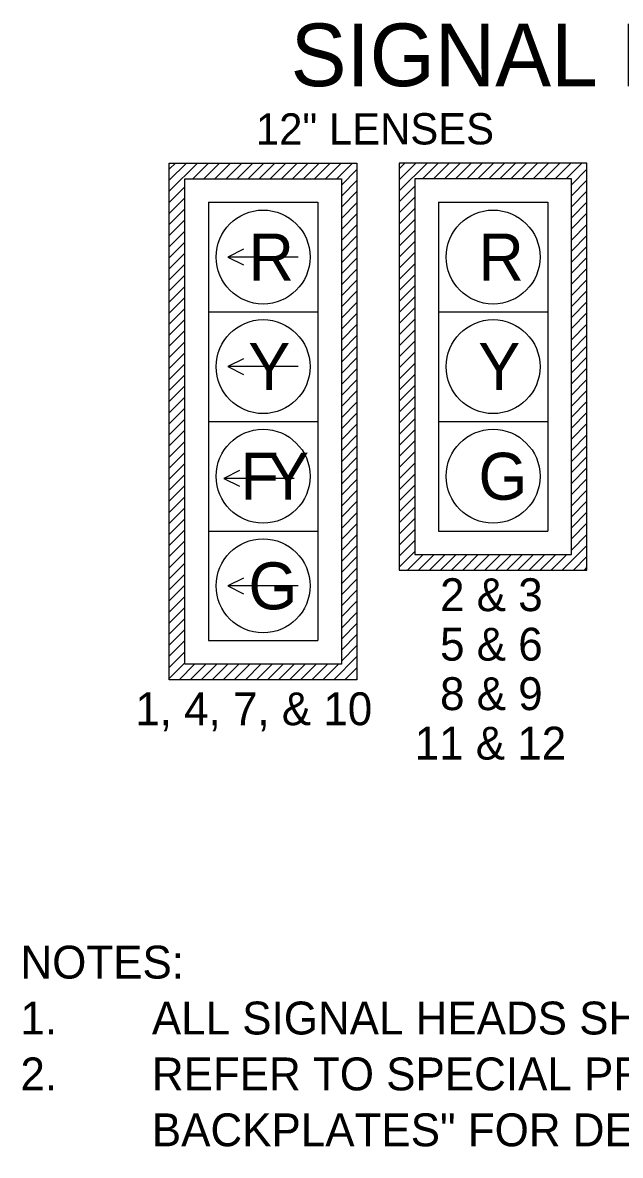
# Model space of a CAD drawing. Extents: x 418532 to 419834, y -565899 to -565285.
# Drawn here: x 419060.8 to 419137.2, y -565430.1 to -565285.5 of the extents above; entities that cross this region are included whole.
import ezdxf

# ---------------------------------------------------------------- set-up
doc = ezdxf.new("R2010")
doc.units = 0
for name, color, linetype in [('C-ANNO-TEXT', 7, 'Continuous'), ('Level 61', 7, 'Continuous'), ('T_Drafting', 7, 'Continuous')]:
    doc.layers.add(name, color=color, linetype=linetype)

msp = doc.modelspace()

# ---------------------------------------------------------------- linework, layer by layer
at = {"layer": 'T_Drafting'}
for p, q in [((419079.58, -565369.4), (419079.58, -565303.4)), ((419079.58, -565303.4), (419103.58, -565303.4)), ((419079.58, -565307), (419083.19, -565303.4)), ((419079.58, -565305.59), (419081.77, -565303.4)), ((419079.58, -565304.18), (419080.36, -565303.4)), ((419082.6, -565305.4), (419084.6, -565303.4)), ((419084.02, -565305.4), (419086.02, -565303.4)), ((419085.43, -565305.4), (419087.43, -565303.4)), ((419086.84, -565305.4), (419088.84, -565303.4)), ((419088.26, -565305.4), (419090.26, -565303.4)), ((419089.67, -565305.4), (419091.67, -565303.4)), ((419091.09, -565305.4), (419093.09, -565303.4)), ((419092.5, -565305.4), (419094.5, -565303.4)), ((419093.92, -565305.4), (419095.92, -565303.4)), ((419095.33, -565305.4), (419097.33, -565303.4)), ((419096.74, -565305.4), (419098.74, -565303.4)), ((419098.16, -565305.4), (419100.16, -565303.4)), ((419099.57, -565305.4), (419101.57, -565303.4)), ((419100.99, -565305.4), (419102.99, -565303.4)), ((419103.58, -565303.4), (419103.58, -565369.4)), ((419132.98, -565303.4), (419108.98, -565303.4)), ((419108.98, -565303.4), (419108.98, -565355.4)), ((419108.98, -565306.94), (419112.53, -565303.4)), ((419108.98, -565305.53), (419111.11, -565303.4)), ((419108.98, -565304.12), (419109.7, -565303.4)), ((419111.94, -565305.4), (419113.94, -565303.4)), ((419113.35, -565305.4), (419115.35, -565303.4)), ((419114.77, -565305.4), (419116.77, -565303.4)), ((419116.18, -565305.4), (419118.18, -565303.4)), ((419117.6, -565305.4), (419119.6, -565303.4)), ((419119.01, -565305.4), (419121.01, -565303.4)), ((419120.42, -565305.4), (419122.42, -565303.4)), ((419121.84, -565305.4), (419123.84, -565303.4)), ((419123.25, -565305.4), (419125.25, -565303.4)), ((419124.67, -565305.4), (419126.67, -565303.4)), ((419126.08, -565305.4), (419128.08, -565303.4)), ((419127.5, -565305.4), (419129.5, -565303.4)), ((419128.91, -565305.4), (419130.91, -565303.4)), ((419130.32, -565305.4), (419132.32, -565303.4)), ((419132.98, -565355.4), (419132.98, -565303.4)), ((419101.58, -565306.22), (419103.58, -565304.22)), ((419130.98, -565306.16), (419132.98, -565304.16)), ((419079.58, -565308.42), (419081.58, -565306.42)), ((419101.58, -565307.63), (419103.58, -565305.63)), ((419108.98, -565308.36), (419110.98, -565306.36)), ((419130.98, -565307.57), (419132.98, -565305.57)), ((419079.58, -565309.83), (419081.58, -565307.83)), ((419101.58, -565309.05), (419103.58, -565307.05)), ((419108.98, -565309.77), (419110.98, -565307.77)), ((419130.98, -565308.99), (419132.98, -565306.99)), ((419079.58, -565311.25), (419081.58, -565309.25)), ((419084.58, -565308.4), (419098.58, -565308.4)), ((419084.58, -565308.4), (419084.58, -565322.4)), ((419098.58, -565308.4), (419098.58, -565322.4)), ((419101.58, -565310.46), (419103.58, -565308.46)), ((419108.98, -565311.19), (419110.98, -565309.19)), ((419113.98, -565308.4), (419127.98, -565308.4)), ((419113.98, -565308.4), (419113.98, -565322.4)), ((419127.98, -565308.4), (419127.98, -565322.4)), ((419130.98, -565310.4), (419132.98, -565308.4)), ((419130.98, -565311.81), (419132.98, -565309.81)), ((419079.58, -565312.66), (419081.58, -565310.66)), ((419101.58, -565311.87), (419103.58, -565309.87)), ((419108.98, -565312.6), (419110.98, -565310.6)), ((419130.98, -565313.23), (419132.98, -565311.23)), ((419079.58, -565314.08), (419081.58, -565312.08)), ((419101.58, -565313.29), (419103.58, -565311.29)), ((419101.58, -565314.7), (419103.58, -565312.7)), ((419108.98, -565314.01), (419110.98, -565312.01)), ((419130.98, -565314.64), (419132.98, -565312.64)), ((419079.58, -565315.49), (419081.58, -565313.49)), ((419101.58, -565316.12), (419103.58, -565314.12)), ((419108.98, -565315.43), (419110.98, -565313.43)), ((419130.98, -565316.06), (419132.98, -565314.06)), ((419079.58, -565316.9), (419081.58, -565314.9)), ((419096.08, -565315.4), (419087.08, -565315.4)), ((419101.58, -565317.53), (419103.58, -565315.53)), ((419108.98, -565316.84), (419110.98, -565314.84)), ((419130.98, -565317.47), (419132.98, -565315.47)), ((419079.58, -565318.32), (419081.58, -565316.32)), ((419101.58, -565318.95), (419103.58, -565316.95)), ((419108.98, -565318.26), (419110.98, -565316.26)), ((419130.98, -565318.88), (419132.98, -565316.88)), ((419079.58, -565319.73), (419081.58, -565317.73)), ((419101.58, -565320.36), (419103.58, -565318.36)), ((419108.98, -565319.67), (419110.98, -565317.67)), ((419130.98, -565320.3), (419132.98, -565318.3)), ((419079.58, -565321.15), (419081.58, -565319.15)), ((419101.58, -565321.77), (419103.58, -565319.77)), ((419108.98, -565321.09), (419110.98, -565319.09)), ((419130.98, -565321.71), (419132.98, -565319.71)), ((419079.58, -565322.56), (419081.58, -565320.56)), ((419101.58, -565323.19), (419103.58, -565321.19)), ((419108.98, -565322.5), (419110.98, -565320.5)), ((419130.98, -565323.13), (419132.98, -565321.13)), ((419079.58, -565323.97), (419081.58, -565321.97)), ((419084.58, -565322.4), (419098.58, -565322.4)), ((419084.58, -565322.4), (419084.58, -565336.4)), ((419098.58, -565322.4), (419098.58, -565336.4)), ((419101.58, -565324.6), (419103.58, -565322.6)), ((419108.98, -565323.91), (419110.98, -565321.91)), ((419113.98, -565322.4), (419127.98, -565322.4)), ((419113.98, -565322.4), (419113.98, -565336.4)), ((419127.98, -565322.4), (419127.98, -565336.4)), ((419130.98, -565324.54), (419132.98, -565322.54)), ((419079.58, -565325.39), (419081.58, -565323.39)), ((419101.58, -565326.02), (419103.58, -565324.02)), ((419108.98, -565325.33), (419110.98, -565323.33)), ((419130.98, -565325.96), (419132.98, -565323.96)), ((419079.58, -565326.8), (419081.58, -565324.8)), ((419101.58, -565327.43), (419103.58, -565325.43)), ((419108.98, -565326.74), (419110.98, -565324.74)), ((419130.98, -565327.37), (419132.98, -565325.37)), ((419079.58, -565328.22), (419081.58, -565326.22)), ((419101.58, -565328.84), (419103.58, -565326.84)), ((419108.98, -565328.16), (419110.98, -565326.16)), ((419130.98, -565328.78), (419132.98, -565326.78)), ((419079.58, -565329.63), (419081.58, -565327.63)), ((419101.58, -565330.26), (419103.58, -565328.26)), ((419108.98, -565329.57), (419110.98, -565327.57)), ((419130.98, -565330.2), (419132.98, -565328.2)), ((419079.58, -565331.05), (419081.58, -565329.05)), ((419096.08, -565329.4), (419087.08, -565329.4)), ((419101.58, -565331.67), (419103.58, -565329.67)), ((419108.98, -565330.99), (419110.98, -565328.99)), ((419130.98, -565331.61), (419132.98, -565329.61)), ((419079.58, -565332.46), (419081.58, -565330.46)), ((419101.58, -565333.09), (419103.58, -565331.09)), ((419108.98, -565332.4), (419110.98, -565330.4)), ((419130.98, -565333.03), (419132.98, -565331.03)), ((419079.58, -565333.87), (419081.58, -565331.87)), ((419101.58, -565334.5), (419103.58, -565332.5)), ((419108.98, -565333.81), (419110.98, -565331.81)), ((419130.98, -565334.44), (419132.98, -565332.44)), ((419079.58, -565335.29), (419081.58, -565333.29)), ((419101.58, -565335.92), (419103.58, -565333.92)), ((419108.98, -565335.23), (419110.98, -565333.23)), ((419130.98, -565335.86), (419132.98, -565333.86)), ((419079.58, -565336.7), (419081.58, -565334.7)), ((419101.58, -565337.33), (419103.58, -565335.33)), ((419108.98, -565336.64), (419110.98, -565334.64)), ((419130.98, -565337.27), (419132.98, -565335.27)), ((419079.58, -565338.12), (419081.58, -565336.12)), ((419084.58, -565336.4), (419098.58, -565336.4)), ((419084.58, -565336.4), (419084.58, -565350.4)), ((419098.58, -565336.4), (419098.58, -565350.4)), ((419101.58, -565338.74), (419103.58, -565336.74)), ((419108.98, -565338.06), (419110.98, -565336.06)), ((419113.98, -565336.4), (419127.98, -565336.4)), ((419113.98, -565336.4), (419113.98, -565350.4)), ((419127.98, -565336.4), (419127.98, -565350.4)), ((419130.98, -565338.68), (419132.98, -565336.68)), ((419079.58, -565339.53), (419081.58, -565337.53)), ((419101.58, -565340.16), (419103.58, -565338.16)), ((419108.98, -565339.47), (419110.98, -565337.47)), ((419130.98, -565340.1), (419132.98, -565338.1)), ((419079.58, -565340.95), (419081.58, -565338.95)), ((419101.58, -565341.57), (419103.58, -565339.57)), ((419108.98, -565340.88), (419110.98, -565338.88)), ((419130.98, -565341.51), (419132.98, -565339.51)), ((419079.58, -565342.36), (419081.58, -565340.36)), ((419101.58, -565342.99), (419103.58, -565340.99)), ((419108.98, -565342.3), (419110.98, -565340.3)), ((419130.98, -565342.93), (419132.98, -565340.93)), ((419079.58, -565343.77), (419081.58, -565341.77)), ((419101.58, -565344.4), (419103.58, -565342.4)), ((419108.98, -565343.71), (419110.98, -565341.71)), ((419130.98, -565344.34), (419132.98, -565342.34)), ((419079.58, -565345.19), (419081.58, -565343.19)), ((419095.56, -565343.67), (419086.56, -565343.67)), ((419101.58, -565345.82), (419103.58, -565343.82)), ((419108.98, -565345.13), (419110.98, -565343.13)), ((419130.98, -565345.75), (419132.98, -565343.75)), ((419079.58, -565346.6), (419081.58, -565344.6)), ((419101.58, -565347.23), (419103.58, -565345.23)), ((419108.98, -565346.54), (419110.98, -565344.54)), ((419108.98, -565347.96), (419110.98, -565345.96)), ((419130.98, -565347.17), (419132.98, -565345.17)), ((419079.58, -565348.02), (419081.58, -565346.02)), ((419079.58, -565349.43), (419081.58, -565347.43)), ((419101.58, -565348.64), (419103.58, -565346.64)), ((419108.98, -565349.37), (419110.98, -565347.37)), ((419130.98, -565348.58), (419132.98, -565346.58)), ((419079.58, -565350.84), (419081.58, -565348.84)), ((419101.58, -565350.06), (419103.58, -565348.06)), ((419108.98, -565350.78), (419110.98, -565348.78)), ((419130.98, -565350), (419132.98, -565348)), ((419079.58, -565352.26), (419081.58, -565350.26)), ((419101.58, -565351.47), (419103.58, -565349.47)), ((419108.98, -565352.2), (419110.98, -565350.2)), ((419130.98, -565351.41), (419132.98, -565349.41)), ((419079.58, -565353.67), (419081.58, -565351.67)), ((419084.58, -565350.4), (419098.58, -565350.4)), ((419084.58, -565350.4), (419084.58, -565364.4)), ((419098.58, -565350.4), (419098.58, -565364.4)), ((419101.58, -565352.89), (419103.58, -565350.89)), ((419108.98, -565353.61), (419110.98, -565351.61)), ((419113.98, -565350.4), (419127.98, -565350.4)), ((419130.98, -565352.83), (419132.98, -565350.83)), ((419079.58, -565355.09), (419081.58, -565353.09)), ((419101.58, -565354.3), (419103.58, -565352.3)), ((419108.98, -565355.03), (419110.98, -565353.03)), ((419129.82, -565355.4), (419132.98, -565352.24)), ((419079.58, -565356.5), (419081.58, -565354.5)), ((419101.58, -565355.71), (419103.58, -565353.71)), ((419110.02, -565355.4), (419112.02, -565353.4)), ((419111.44, -565355.4), (419113.44, -565353.4)), ((419112.85, -565355.4), (419114.85, -565353.4)), ((419114.27, -565355.4), (419116.27, -565353.4)), ((419115.68, -565355.4), (419117.68, -565353.4)), ((419117.09, -565355.4), (419119.09, -565353.4)), ((419118.51, -565355.4), (419120.51, -565353.4)), ((419119.92, -565355.4), (419121.92, -565353.4)), ((419121.34, -565355.4), (419123.34, -565353.4)), ((419122.75, -565355.4), (419124.75, -565353.4)), ((419124.16, -565355.4), (419126.16, -565353.4)), ((419125.58, -565355.4), (419127.58, -565353.4)), ((419126.99, -565355.4), (419128.99, -565353.4)), ((419128.41, -565355.4), (419130.41, -565353.4)), ((419131.24, -565355.4), (419132.98, -565353.65)), ((419079.58, -565357.92), (419081.58, -565355.92)), ((419101.58, -565357.13), (419103.58, -565355.13)), ((419108.98, -565355.4), (419132.98, -565355.4)), ((419132.65, -565355.4), (419132.98, -565355.07)), ((419079.58, -565359.33), (419081.58, -565357.33)), ((419096.08, -565357.4), (419087.08, -565357.4)), ((419101.58, -565358.54), (419103.58, -565356.54)), ((419079.58, -565360.74), (419081.58, -565358.74)), ((419101.58, -565359.96), (419103.58, -565357.96)), ((419079.58, -565362.16), (419081.58, -565360.16)), ((419101.58, -565361.37), (419103.58, -565359.37)), ((419079.58, -565363.57), (419081.58, -565361.57)), ((419101.58, -565362.79), (419103.58, -565360.79)), ((419079.58, -565364.99), (419081.58, -565362.99)), ((419101.58, -565364.2), (419103.58, -565362.2)), ((419079.58, -565366.4), (419081.58, -565364.4)), ((419084.58, -565364.4), (419098.58, -565364.4)), ((419101.58, -565365.61), (419103.58, -565363.61)), ((419079.58, -565367.82), (419081.58, -565365.82)), ((419101.58, -565367.03), (419103.58, -565365.03)), ((419079.58, -565369.23), (419081.58, -565367.23)), ((419080.83, -565369.4), (419082.83, -565367.4)), ((419082.24, -565369.4), (419084.24, -565367.4)), ((419083.66, -565369.4), (419085.66, -565367.4)), ((419085.07, -565369.4), (419087.07, -565367.4)), ((419086.48, -565369.4), (419088.48, -565367.4)), ((419087.9, -565369.4), (419089.9, -565367.4)), ((419089.31, -565369.4), (419091.31, -565367.4)), ((419090.73, -565369.4), (419092.73, -565367.4)), ((419092.14, -565369.4), (419094.14, -565367.4)), ((419093.56, -565369.4), (419095.56, -565367.4)), ((419094.97, -565369.4), (419096.97, -565367.4)), ((419096.38, -565369.4), (419098.38, -565367.4)), ((419097.8, -565369.4), (419099.8, -565367.4)), ((419099.21, -565369.4), (419101.21, -565367.4)), ((419100.63, -565369.4), (419103.58, -565366.44)), ((419102.04, -565369.4), (419103.58, -565367.86)), ((419103.58, -565369.4), (419079.58, -565369.4)), ((419103.45, -565369.4), (419103.58, -565369.27))]:
    msp.add_line(p, q, dxfattribs=at)
for points in [[(419081.58, -565367.4), (419081.58, -565305.4), (419101.58, -565305.4), (419101.58, -565367.4)], [(419130.98, -565353.4), (419130.98, -565305.4), (419110.98, -565305.4), (419110.98, -565353.4)]]:
    msp.add_lwpolyline(points, close=True, dxfattribs=at)
for points in [[(419089.08, -565314.4), (419087.08, -565315.4), (419089.08, -565316.4)], [(419089.08, -565328.4), (419087.08, -565329.4), (419089.08, -565330.4)], [(419088.56, -565342.67), (419086.56, -565343.67), (419088.56, -565344.67)], [(419089.08, -565356.4), (419087.08, -565357.4), (419089.08, -565358.4)]]:
    msp.add_lwpolyline(points, dxfattribs=at)
for centre in [(419091.58, -565315.4), (419120.98, -565315.4), (419091.58, -565329.4), (419120.98, -565329.4), (419091.58, -565343.4), (419120.98, -565343.4), (419091.58, -565357.4)]:
    msp.add_circle(centre, 6, dxfattribs=at)

# ---------------------------------------------------------------- texts
at = {"layer": 'C-ANNO-TEXT'}
for s, p in [('2 & 3', (419114.2, -565360.63)), ('5 & 6', (419114.2, -565366.95)), ('8 & 9', (419114.2, -565373.27)), ('1, 4, 7, & 10', (419075.24, -565375.2)), ('11 & 12', (419110.96, -565379.59))]:
    msp.add_text(s, height=4.2, rotation=360, dxfattribs=at).set_placement(p)
for s, p in [('NOTES:', (419060.56, -565407.56)), ('1.', (419060.56, -565414.7)), ('ALL SIGNAL HEADS SHALL HAVE BACKPLATES.', (419077.36, -565414.7)), ('2.', (419060.56, -565421.84)), ('REFER TO SPECIAL PROVISION "RETROREFLECTIVE', (419077.36, -565421.84)), ('BACKPLATES" FOR DETAILS ON REQUIREMENTS FOR ', (419077.36, -565428.98))]:
    msp.add_text(s, height=4.2, dxfattribs=at).set_placement(p)
at = {"layer": 'Level 61'}
msp.add_text('SIGNAL FACES', height=8, dxfattribs=at).set_placement((419095.1, -565293.58))
msp.add_text('12" LENSES', height=4, rotation=0.072, dxfattribs=at).set_placement((419090.66, -565301.05))
at = {"layer": 'T_Drafting'}
for s, p in [('R', (419089.72, -565318.4)), ('R', (419119.11, -565318.4)), ('Y', (419089.69, -565332.4)), ('Y', (419119.09, -565332.4)), ('F', (419088.68, -565346.4)), ('Y', (419092.1, -565346.4)), ('G', (419119.11, -565346.4)), ('G', (419089.71, -565360.4))]:
    msp.add_text(s, height=6, dxfattribs=at).set_placement(p)

doc.saveas('drawing.dxf')
